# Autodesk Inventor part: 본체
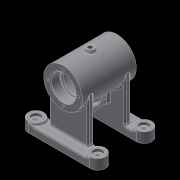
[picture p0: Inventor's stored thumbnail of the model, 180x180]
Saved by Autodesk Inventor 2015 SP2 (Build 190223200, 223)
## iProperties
Created: 2015-11
Part Number: 본체
Material: 일반
Document SubType Name: Modeling
Designer: AMC
Density: 1 g/cm^3
Appearance: 기본값
Author: AMC
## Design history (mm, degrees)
sketch "스케치2"
  geometry: L1 (-40, 30)-(40, 30); L2 (-40, 20)-(40, 20); L3 (40, 40)-(-40, 40); A1 r 10 centre (-40, 30) between (-40, 40) and (-40, 20); A2 r 10 centre (40, 30) between (40, 20) and (40, 40); 2 further points
  constraints: 8 end point, 4 point on circle, 4 tangent, 2 centre point, 1 horizontal, 1 midpoint, 1 parallel, 1 vertical alignment
  dimensions: "d8" = 20 distance between parallel lines of L2 L3; "d11" = 80 distance of L3.start L3.end; "d13" = 40 distance from line of point (0, 0) L3
extrude "돌출1" new body sketch "스케치2" distance "d14" = 10; taper "d15" = 0 deg
sketch "스케치3"
  geometry: C1 r 10 at (40, 30); C2 r 10 at (-40, 30); A1 r 10 centre (-40, 30) between (-40, 40) and (-40, 20) reference; A2 r 10 centre (40, 30) between (40, 20) and (40, 40) reference; 1 further point
  constraints: 4 concentric, 2 centre point
extrude "돌출2" join sketch "스케치3" distance "d16" = 3; taper "d17" = 0 deg
hole "구멍1" diameter "d20" = 12; stored, may be unused: countersink angle "d24" = 90 deg, drill point angle "d26" = 0 deg; dims "d18" = 10, "d19" = 10, "d21" = 6, "d22" = 4, "d23" = 2, "d25" = 4
hole "구멍2" diameter "d29" = 6; stored, may be unused: countersink angle "d33" = 90 deg, drill point angle "d35" = 0 deg; dims "d27" = 10, "d28" = 10, "d30" = 6, "d31" = 4, "d32" = 2, "d34" = 4
chamfer "모따기1" distance "d36" = 1; stored, may be unused: second distance "d37" = 2, angle "d38" = 45 deg
fillet "모깎기1" dims "d39" = 0.3
fillet "모깎기3" dims "d41" = 2
fillet "모깎기4" dims "d42" = 2
sketch "스케치4"
  geometry: L1 (-25, 20)-(25, 20); L2 (25, 20)-(25, 28); L3 (25, 28)-(-25, 28); L4 (-25, 28)-(-25, 20); L5 (-33.367, 20)-(33.367, 20) reference; 2 further points
  constraints: 8 end point, 2 parallel, 1 collinear, 1 horizontal, 1 midpoint, 1 perpendicular, 1 vertical alignment
  dimensions: "d43" = 50 distance of L1.start L1.end; "d44" = 8 distance between parallel lines of L3 L1
extrude "돌출3" join sketch "스케치4" distance "d45" = 58; taper "d46" = 0 deg
sketch "스케치7"
  geometry: L1 (-40, 0)-(40, 0) reference; C1 r 25 at (0, 68); 1 further point
  constraints: 1 centre point
  dimensions: "d58" = 68 distance from line of L1 C1.centre; "d59" = 50 diameter of C1
extrude "돌출6" join sketch "스케치7" stored distance "d60" = 70; taper "d61" = 0 deg
node "작업 평면3"
sketch "스케치8"
  geometry: C1 r 5 at (0, 0); 1 further point
  constraints: 1 centre point, 1 coincident
  dimensions: "d63" = 10 diameter of C1
extrude "돌출7" join sketch "스케치8" stored distance "d64" = 70; taper "d65" = 0 deg
node "작업 평면4"
  node "작업축2"
sketch "스케치9"
  geometry: L1 (-56.011, 0)-(56.011, 0) reference; C1 r 6 at (0, 0); 1 further point
  constraints: 1 centre point, 1 midpoint, 1 vertical alignment
  dimensions: "d67" = 12 diameter of C1
extrude "돌출8" join sketch "스케치9" distance "d68" = 28; taper "d69" = 0 deg
sketch "스케치10"
  geometry: L1 (-17.206, 23)-(20, 23); L2 (-35, 43)-(35, 43) reference; L3 (20, 10)-(20, 68) reference; 1 further point
  constraints: 2 end point, 1 horizontal, 1 point on line
  dimensions: "d70" = 20 distance between parallel lines of L1 L2
feature "리브1" sketch "스케치10" dims "d71" = 1, "d72" = 8, "d73" = 0, "d74" = 0, "d75" = 1, "d76" = 1
sketch "스케치11"
  geometry: L1 (-35, 84)-(-23, 84); L2 (-23, 84)-(-23, 82); L3 (-23, 82)-(-21, 82); L4 (-21, 82)-(-21, 89); L5 (-21, 89)-(21, 89); L6 (21, 89)-(21, 82); L7 (21, 82)-(23, 82); L8 (23, 82)-(23, 84); L9 (23, 84)-(35, 84); L10 (35, 84)-(35, 68); L11 (35, 68)-(-35, 68); L12 (-35, 68)-(-35, 84); L13 (-35, 93)-(-35, 43) reference; L14 (35, 43)-(35, 93) reference; 1 further point
  constraints: 24 end point, 8 perpendicular, 4 point on line, 2 collinear, 1 horizontal, 1 vertical
  dimensions: "d77" = 32 diameter of L9 L11; "d78" = 42 diameter of L5 L11; "d79" = 2 distance between parallel lines of L8 L6; "d80" = 2 distance between parallel lines of L4 L2; "d81" = 12 distance between parallel lines of L10 L8; "d82" = 12 distance between parallel lines of L2 L12; "d83" = 28 diameter of L7 L11; "d84" = 136 diameter of point (0, 0) L11
revolve "회전1" sketch "스케치11" stored, may be unused: angle "d85" = 90 deg
fillet "모깎기7" dims "d86" = 0.3
fillet "모깎기8" dims "d87" = 3
hole "구멍3" diameter "d90" = 5.188; stored, may be unused: countersink angle "d94" = 90 deg, drill point angle "d96" = 0 deg; dims "d88" = 10, "d89" = 10, "d91" = 12, "d92" = 4, "d93" = 2, "d95" = 16
hole "구멍4" diameter "d99" = 5.188; stored, may be unused: countersink angle "d103" = 90 deg, drill point angle "d105" = 0 deg; dims "d97" = 10, "d98" = 10, "d100" = 12, "d101" = 4, "d102" = 2, "d104" = 16
sketch "스케치12" dims "d106" = 40
  geometry: C1 r 25 at (0, 0) reference; 3 further points
  constraints: 2 horizontal alignment, 3 other
hole "구멍5" sketch "스케치12" at (20, 0) diameter "d107" = 3.242; stored, may be unused: countersink angle "d111" = 90 deg, drill point angle "d113" = 118 deg; dims "d108" = 8, "d109" = 4, "d110" = 2, "d112" = 10
sketch "스케치13"
  geometry: L1 (10.322, 12)-(10.322, 28); L2 (13.822, 12)-(13.822, 28); L3 (6.822, 28)-(6.822, 12); L4 (43.322, 60)-(43.322, 40) reference; A1 r 3.5 centre (10.322, 12) between (6.822, 12) and (13.822, 12); A2 r 3.5 centre (10.322, 28) between (13.822, 28) and (6.822, 28); 2 further points
  constraints: 8 end point, 4 point on circle, 4 tangent, 2 centre point, 1 horizontal alignment, 1 midpoint, 1 parallel, 1 vertical
  dimensions: "d117" = 33 distance between parallel lines of L4 L1; "d118" = 3.5 radius of A2; "d119" = 23 dimension on A2 A1
extrude "돌출9" cut sketch "스케치13" stored distance "d120" = 28; taper "d121" = 0 deg
fillet "모깎기10" dims "d123" = 2
fillet "모깎기11" dims "d124" = 2
fillet "모깎기12" dims "d125" = 2
fillet "모깎기13" dims "d126" = 2
fillet "모깎기14" dims "d127" = 2
node "작업 평면5"
sketch "스케치14"
  geometry: L1 (-25, 5)-(25, 5); L2 (25, 5)-(25, -5); L3 (25, -5)-(-25, -5); L4 (-25, -5)-(-25, 5); L5 (25, 0)-(-25, 0); L6 (0, -5)-(0, 5); L7 (35, 25)-(-35, 25) reference; L8 (-35, 25)-(-35, -25) reference; 1 further point
  constraints: 4 end point, 4 midpoint, 2 other
  dimensions: "d128" = 50 distance of L1.start L1.end; "d129" = 10 distance between parallel lines of L1 L3; "d130" = 25 distance between parallel lines of L7 L5; "d131" = 35 distance between parallel lines of L8 L6
feature "엠보싱1" sketch "스케치14" dims "d22" = 4, "d132" = 0.5, "d133" = 0
chamfer "모따기2" distance "d134" = 1; stored, may be unused: second distance "d135" = 2, angle "d136" = 45 deg
fillet "모깎기15" dims "d137" = 3.5
fillet "모깎기16" dims "d138" = 3.5
node "솔리드1"
mirror "대칭1"
mirror "대칭2"
pattern_circular "원형 패턴1" dims angle "d115" = 360 deg
mirror "대칭3"
other parameters: "d62" = 96, "d66" = 60 deg
